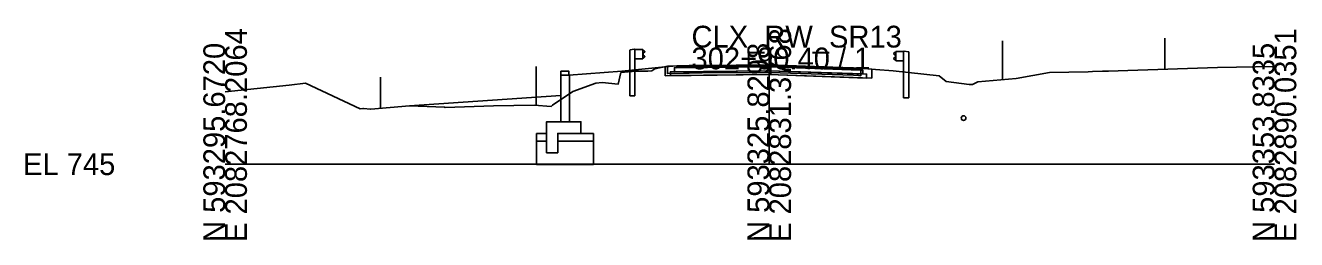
# Model space of a CAD drawing. Extents: x -26 to 2138, y -10 to 4518.
# Drawn here: x -25.7 to 137.8, y 4490.3 to 4517.8 of the extents above; entities that cross this region are included whole.
import ezdxf

# ---------------------------------------------------------------- set-up
doc = ezdxf.new("R2010")
doc.units = 0
for name, color, linetype in [('DR_P_Erosion_Control', 7, 'Continuous'), ('GK_Cells', 7, 'Continuous'), ('MD_P_Surface_Aggregate_Base', 7, 'Continuous'), ('MD_P_Surface_Asphalt_Concrete_Base', 7, 'Continuous'), ('MD_P_Surface_Asphalt_Concrete_Intermediate_Course', 7, 'Continuous'), ('MD_P_Surface_Asphalt_Concrete_Surface_Course', 7, 'Continuous'), ('MD_P_Surface_Non-Reinforced_Concrete_Pavement', 7, 'Continuous'), ('MD_X_Asphalt_Pavement', 7, 'Continuous'), ('RD_P_Cells', 7, 'Continuous'), ('RW_P_Esmt_SH', 7, 'Continuous'), ('RW_X_Esmt_SH', 7, 'Continuous'), ('SC_Scratch1', 7, 'Continuous'), ('UT_X_Water', 7, 'Continuous'), ('XS_P_Excavation_Limits', 7, 'Continuous'), ('XS_P_Finished_Grade', 7, 'Continuous'), ('XS_P_Subgrade', 7, 'Continuous'), ('XS_X_Ground_Line', 7, 'Continuous')]:
    doc.layers.add(name, color=color, linetype=linetype)

msp = doc.modelspace()

# ---------------------------------------------------------------- linework, layer by layer
at = {"layer": 'DR_P_Erosion_Control'}
msp.add_line((43.19, 4508.82), (23.72, 4507.52), dxfattribs=at)
at = {"layer": 'GK_Cells'}
for p, q in [((70, 4500), (70, 4515)), ((0, 4500), (70, 4500)), ((70, 4500), (135, 4500))]:
    msp.add_line(p, q, dxfattribs=at)
at = {"layer": 'MD_P_Surface_Aggregate_Base'}
for points in [[(70, 4512.02), (70, 4511.52), (57.29, 4511.39), (57.29, 4511.89), (70, 4512.02)], [(70, 4512.02), (70, 4511.52), (82.53, 4511.08), (82.53, 4511.58), (70, 4512.02)]]:
    msp.add_lwpolyline(points, dxfattribs=at)
at = {"layer": 'MD_P_Surface_Asphalt_Concrete_Base'}
for points in [[(70, 4512.52), (70, 4512.02), (57.79, 4511.89), (57.79, 4512.39), (70, 4512.52)], [(70, 4512.52), (70, 4512.02), (82.03, 4511.6), (82.03, 4512.1), (81.7, 4512.11), (70, 4512.52)]]:
    msp.add_lwpolyline(points, dxfattribs=at)
at = {"layer": 'MD_P_Surface_Asphalt_Concrete_Intermediate_Course'}
for points in [[(70, 4512.66), (70, 4512.52), (58.12, 4512.4), (58.12, 4512.54), (70, 4512.66)], [(70, 4512.66), (70, 4512.52), (81.7, 4512.11), (81.7, 4512.26), (70, 4512.66)]]:
    msp.add_lwpolyline(points, dxfattribs=at)
at = {"layer": 'MD_P_Surface_Asphalt_Concrete_Surface_Course'}
for points in [[(70, 4512.77), (70, 4512.66), (58.12, 4512.54), (58.12, 4512.65), (70, 4512.77)], [(70, 4512.77), (70, 4512.66), (81.7, 4512.26), (81.7, 4512.36), (70, 4512.77)]]:
    msp.add_lwpolyline(points, dxfattribs=at)
at = {"layer": 'MD_P_Surface_Non-Reinforced_Concrete_Pavement'}
for points in [[(43.19, 4511.46), (44.22, 4511.46), (44.22, 4511.96), (43.19, 4511.96), (43.19, 4511.46)], [(44.3, 4505.46), (44.3, 4511.46), (43.19, 4511.46), (43.19, 4505.46), (44.3, 4505.46)], [(41.58, 4505.46), (41.56, 4505.46), (41.35, 4505.46), (41.35, 4502.65), (41.35, 4501.46), (41.52, 4501.46), (41.58, 4501.46), (42.79, 4501.46), (42.79, 4503.01), (42.79, 4503.96), (43.93, 4503.96), (45.77, 4503.96), (45.77, 4504.99), (45.77, 4505.46), (41.58, 4505.46)]]:
    msp.add_lwpolyline(points, dxfattribs=at)
at = {"layer": 'MD_X_Asphalt_Pavement'}
msp.add_lwpolyline([(56.89, 4512.6), (56.89, 4511.64), (58.98, 4511.69), (59.71, 4511.72), (61.39, 4511.73), (70.12, 4511.81), (74.04, 4511.66), (80.84, 4511.43), (81.48, 4511.39), (81.78, 4511.37), (81.78, 4512.33), (81.48, 4512.35), (80.84, 4512.39), (74.04, 4512.62), (70.12, 4512.76), (61.39, 4512.69), (59.71, 4512.67), (58.98, 4512.65), (56.89, 4512.6)], dxfattribs=at)
at = {"layer": 'RD_P_Cells'}
for p, q in [((52.1, 4514.69), (52.05, 4514.67)), ((52.05, 4508.78), (52.05, 4514.67)), ((52.64, 4514.78), (52.1, 4514.69)), ((52.72, 4514.73), (52.64, 4514.78)), ((53.72, 4514.73), (52.72, 4514.73)), ((52.72, 4508.78), (52.72, 4514.73)), ((53.72, 4513.55), (52.72, 4513.55)), ((53.72, 4513.55), (53.72, 4514.73)), ((53.81, 4514.64), (53.72, 4514.65)), ((53.72, 4513.63), (53.81, 4513.65)), ((53.73, 4514.14), (53.73, 4514.19)), ((53.73, 4514.09), (53.73, 4514.14)), ((53.76, 4514.25), (53.97, 4514.39)), ((53.97, 4513.89), (53.76, 4514.03)), ((53.97, 4514.52), (53.81, 4514.64)), ((53.81, 4513.65), (53.97, 4513.76)), ((86.03, 4514.28), (86.19, 4514.39)), ((86.24, 4514.01), (86.03, 4514.15)), ((86.03, 4513.64), (86.24, 4513.79)), ((86.19, 4513.4), (86.03, 4513.52)), ((86.19, 4514.39), (86.28, 4514.41)), ((86.27, 4513.9), (86.27, 4513.94)), ((86.27, 4513.85), (86.27, 4513.9)), ((86.28, 4513.3), (86.28, 4514.49)), ((86.28, 4514.49), (87.28, 4514.49)), ((87.28, 4514.49), (87.36, 4514.53)), ((87.28, 4508.53), (87.28, 4514.49)), ((87.36, 4514.53), (87.9, 4514.45)), ((87.9, 4514.45), (87.95, 4514.43)), ((87.95, 4508.53), (87.95, 4514.43)), ((86.28, 4513.39), (86.19, 4513.4)), ((86.28, 4513.3), (87.28, 4513.3)), ((52.72, 4508.78), (52.05, 4508.78)), ((87.28, 4508.53), (87.95, 4508.53))]:
    msp.add_line(p, q, dxfattribs=at)
for points in [[(53.74, 4514.2), (53.74, 4514.08), (53.73, 4514.08), (53.73, 4514.2)], [(53.74, 4514.17), (53.74, 4514.11), (53.76, 4514.11), (53.76, 4514.17)], [(86.26, 4513.93), (86.26, 4513.87), (86.24, 4513.87), (86.24, 4513.93)], [(86.26, 4513.96), (86.26, 4513.84), (86.27, 4513.84), (86.27, 4513.96)]]:
    msp.add_lwpolyline(points, close=True, dxfattribs=at)
for centre, start, end in [((53.81, 4514.19), 124.962, 180), ((53.81, 4514.09), 180, 235.038), ((53.92, 4514.46), 304.962, 54.7677), ((53.92, 4513.82), 304.962, 54.7677), ((86.08, 4514.22), 125.2323, 235.038), ((86.08, 4513.58), 125.2323, 235.038), ((86.19, 4513.94), 0, 55.038), ((86.19, 4513.85), 304.962, 0)]:
    msp.add_arc(centre, 0.0781, start, end, dxfattribs=at)
at = {"layer": 'RW_P_Esmt_SH'}
for p, q in [((120.87, 4512.22), (120.87, 4516.22)), ((20, 4507.18), (20, 4511.18))]:
    msp.add_line(p, q, dxfattribs=at)
at = {"layer": 'RW_X_Esmt_SH'}
for p, q in [((100, 4510.86), (100, 4515.86)), ((40, 4507.55), (40, 4512.55))]:
    msp.add_line(p, q, dxfattribs=at)
at = {"layer": 'SC_Scratch1'}
for p, q in [((58.12, 4512.65), (56.62, 4512.5)), ((70, 4512.02), (57.29, 4511.89)), ((57.29, 4511.89), (57.29, 4511.39)), ((70, 4512.52), (57.79, 4512.39)), ((57.79, 4512.39), (57.79, 4511.89)), ((70, 4512.77), (58.12, 4512.65)), ((70, 4512.66), (58.12, 4512.54)), ((58.12, 4512.65), (58.12, 4512.4)), ((70, 4512.77), (81.7, 4512.36)), ((70, 4512.66), (81.7, 4512.26)), ((70, 4512.52), (82.03, 4512.1)), ((70, 4512.02), (82.53, 4511.58)), ((81.7, 4512.36), (81.7, 4512.11)), ((81.7, 4512.36), (83.2, 4512.23)), ((82.03, 4512.1), (82.03, 4511.6)), ((82.53, 4511.58), (82.53, 4511.08))]:
    msp.add_line(p, q, dxfattribs=at)
at = {"layer": 'UT_X_Water'}
msp.add_circle((95, 4505.93), 0.3, dxfattribs=at)
at = {"layer": 'XS_P_Excavation_Limits'}
for p, q in [((40.07, 4499.96), (40.07, 4503.96)), ((41.35, 4503.96), (40.07, 4503.96)), ((45.77, 4503.96), (47.4, 4503.96)), ((47.4, 4499.96), (47.4, 4503.96)), ((40.07, 4502.96), (41.35, 4502.96)), ((42.79, 4502.96), (47.4, 4502.96)), ((40.07, 4499.96), (47.4, 4499.96))]:
    msp.add_line(p, q, dxfattribs=at)
at = {"layer": 'XS_P_Finished_Grade'}
for p, q in [((51.05, 4511.94), (44.22, 4511.46)), ((56.62, 4512.5), (51.05, 4511.94))]:
    msp.add_line(p, q, dxfattribs=at)
at = {"layer": 'XS_P_Subgrade'}
for p, q in [((56.62, 4512.5), (56.62, 4511.38)), ((83.2, 4512.23), (83.2, 4511.06)), ((70, 4511.52), (56.62, 4511.38)), ((70, 4511.52), (83.2, 4511.06))]:
    msp.add_line(p, q, dxfattribs=at)
at = {"layer": 'XS_X_Ground_Line'}
msp.add_lwpolyline([(0, 4509.32), (8.25, 4510.15), (10.35, 4510.42), (17.39, 4507.12), (17.72, 4507.14), (17.79, 4507.14), (18.71, 4507.06), (18.73, 4507.07), (23.72, 4507.52), (28.22, 4507.32), (28.29, 4507.31), (34.52, 4507.49), (39.77, 4507.57), (41.93, 4507.4), (42.11, 4507.58), (44.75, 4509.36), (47.68, 4510.41), (48.52, 4510.49), (50.57, 4510.3), (50.91, 4511.78), (52.84, 4511.94), (54.39, 4511.98), (54.89, 4511.99), (55.28, 4512.26), (56.89, 4512.6), (58.98, 4512.65), (59.71, 4512.67), (61.39, 4512.69), (70.12, 4512.76), (74.04, 4512.62), (80.84, 4512.39), (81.48, 4512.35), (81.78, 4512.33), (83.65, 4512.19), (85.96, 4512), (91.84, 4511.37), (92.76, 4510.62), (95.7, 4510.26), (96.16, 4510.26), (96.84, 4510.57), (101.75, 4511.03), (106.06, 4511.78), (111.02, 4511.88), (111.58, 4511.9), (112.86, 4511.95), (113.63, 4511.97), (116.15, 4512.06), (127.65, 4512.45), (135, 4512.57)], dxfattribs=at)

# ---------------------------------------------------------------- texts
msp.add_text('-', height=0.0001).set_placement((0, 4500))
at = {"layer": 'GK_Cells'}
for s, p in [('E 2082768.2064', (2.8, 4490)), ('E 2082831.3768', (72.8, 4490)), ('E 2082890.0351', (137.8, 4490)), ('N 593295.6720', (0, 4490)), ('N 593325.8298', (70, 4490)), ('N 593353.8335', (135, 4490))]:
    msp.add_text(s, height=2.8, rotation=90, dxfattribs=at).set_placement(p)
for s, p in [('CLX_RW_SR13', (60, 4515)), ('302+90.40 / 1', (60, 4512.2)), ('EL 745', (-26, 4498.6))]:
    msp.add_text(s, height=2.8, dxfattribs=at).set_placement(p)

doc.saveas('drawing.dxf')
